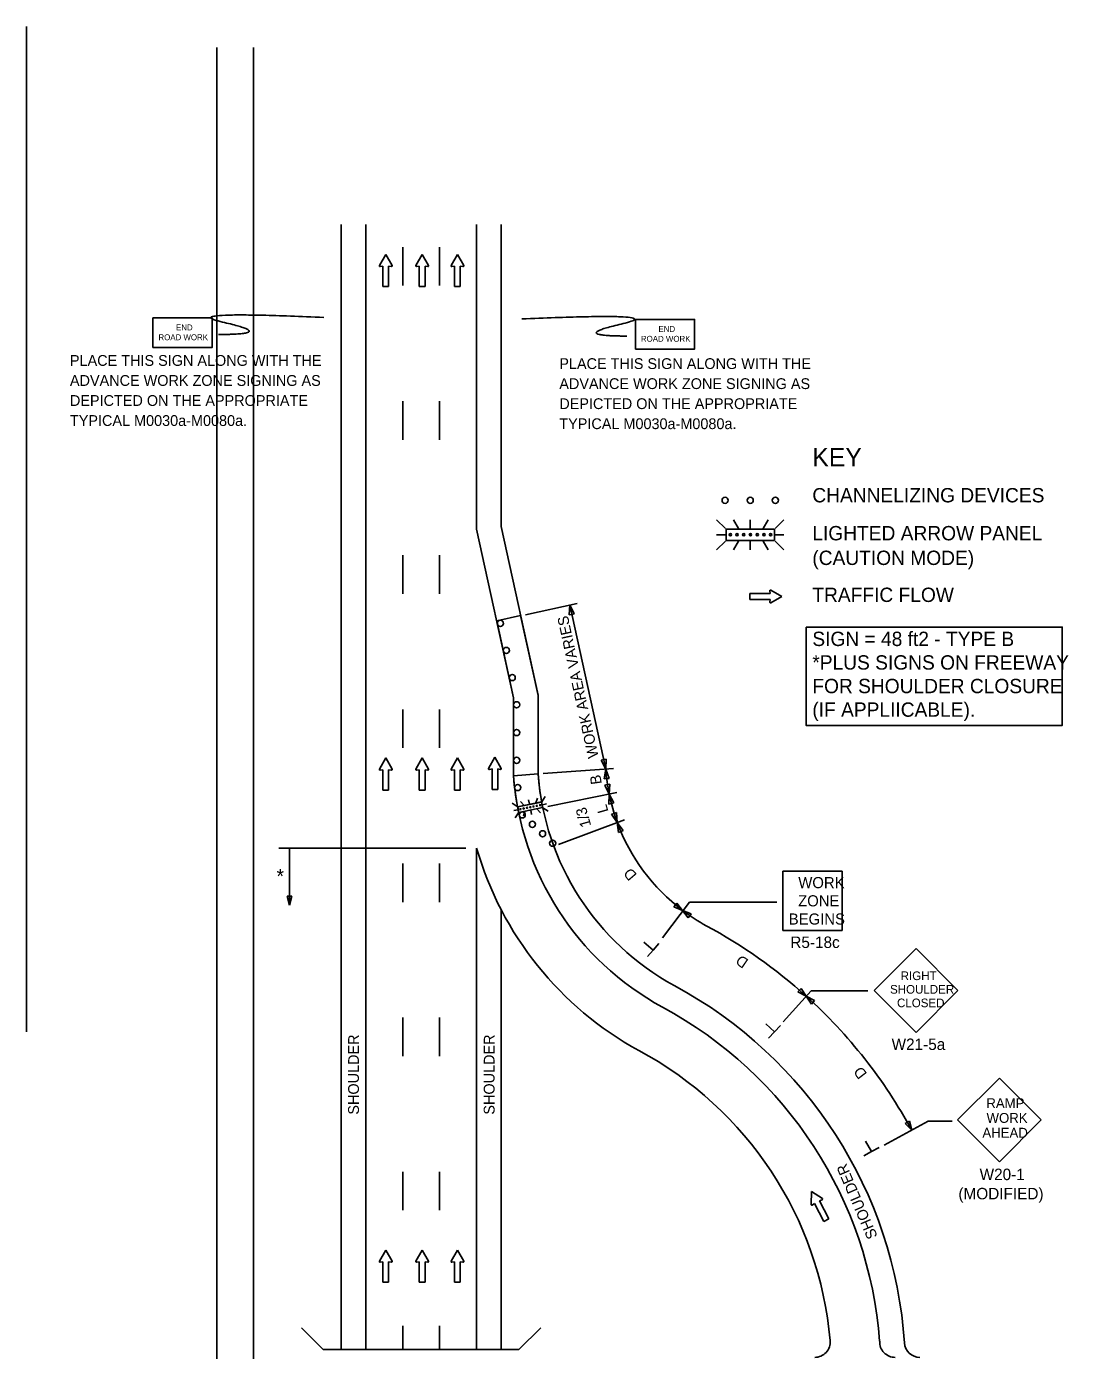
# Model space of a CAD drawing. Extents: x 16733 to 18471, y 4586 to 5876.
# Drawn here: x 16733 to 17409, y 5017 to 5876 of the extents above; entities that cross this region are included whole.
import ezdxf

# ---------------------------------------------------------------- set-up
doc = ezdxf.new("R2010")
doc.units = 0
for name, color, linetype in [('BORDER', 7, 'Continuous'), ('Level 10', 7, 'Continuous'), ('MT_SCRATCH_LEVEL_E', 7, 'Continuous'), ('PAVT_EDGE_EX', 7, 'Continuous'), ('TRAFFIC_SIGNS_PR', 7, 'Continuous'), ('TYPICAL_TEXT_DIMEN_EX', 7, 'Continuous')]:
    doc.layers.add(name, color=color, linetype=linetype)

msp = doc.modelspace()

# ---------------------------------------------------------------- linework, layer by layer
at = {"layer": 'BORDER'}
for p, q in [((17090.28, 5501.48), (17056.67, 5494.14)), ((17085.46, 5500.43), (17085.05, 5493.97)), ((17108.72, 5394.01), (17085.46, 5500.43)), ((17088.34, 5494.63), (17085.46, 5500.43)), ((17053.51, 5493.52), (17037.95, 5490.12)), ((17085.05, 5493.97), (17086.69, 5494.3)), ((17086.69, 5494.3), (17088.34, 5494.63)), ((17107.42, 5400.12), (17105.78, 5399.78)), ((17105.78, 5399.78), (17108.72, 5394.01)), ((17109.06, 5400.47), (17107.42, 5400.12)), ((17108.72, 5394.01), (17109.06, 5400.47)), ((17064.83, 5390.79), (17048.88, 5389.63)), ((17113.69, 5394.37), (17068.13, 5391.03)), ((17108.72, 5394.01), (17107.64, 5387.62)), ((17107.64, 5387.62), (17109.31, 5387.78)), ((17110.97, 5387.94), (17108.72, 5394.01)), ((17109.31, 5387.78), (17110.97, 5387.94)), ((17115.87, 5378.73), (17071.1, 5369.62)), ((17109.74, 5383.87), (17108.1, 5383.54)), ((17108.1, 5383.54), (17110.98, 5377.74)), ((17111.38, 5384.2), (17109.74, 5383.87)), ((17110.98, 5377.74), (17111.38, 5384.2)), ((17051.46, 5369.47), (17067.14, 5372.66)), ((17110.98, 5377.74), (17110.82, 5371.27)), ((17110.82, 5371.27), (17112.45, 5371.66)), ((17114.07, 5372.05), (17110.98, 5377.74)), ((17112.45, 5371.66), (17114.07, 5372.05)), ((17114.15, 5365.17), (17112.57, 5364.6)), ((17112.57, 5364.6), (17116.26, 5359.28)), ((17115.72, 5365.73), (17114.15, 5365.17)), ((17116.26, 5359.28), (17115.72, 5365.73)), ((17120.93, 5361.02), (17078.1, 5345.12)), ((17120.14, 5354.1), (17116.26, 5359.28)), ((17116.26, 5359.28), (17117.03, 5352.85)), ((17117.03, 5352.85), (17118.58, 5353.48)), ((17118.58, 5353.48), (17120.14, 5354.1)), ((17017.95, 5342.66), (16896.59, 5342.66)), ((16903.58, 5342.66), (16903.58, 5305.56)), ((16901.96, 5311.41), (16903.53, 5311.43)), ((16903.58, 5305.56), (16901.96, 5311.41)), ((16903.53, 5311.43), (16905.1, 5311.44)), ((16905.1, 5311.44), (16903.58, 5305.56)), ((17145.63, 5284.47), (17163.07, 5307.63)), ((17152.99, 5304.52), (17153.94, 5305.77)), ((17158.61, 5302.23), (17152.99, 5304.52)), ((17153.94, 5305.77), (17154.89, 5307.02)), ((17154.89, 5307.02), (17158.61, 5302.23)), ((17162.34, 5297.44), (17158.61, 5302.23)), ((17158.61, 5302.23), (17164.23, 5299.94)), ((17163.07, 5307.63), (17219.84, 5307.63)), ((17163.29, 5298.69), (17162.34, 5297.44)), ((17164.23, 5299.94), (17163.29, 5298.69)), ((17139.46, 5276.54), (17133.56, 5281.61)), ((17139.46, 5276.54), (17135.8, 5272.27)), ((17143.13, 5280.8), (17139.46, 5276.54)), ((17223.88, 5229.94), (17242.07, 5250.08)), ((17233.51, 5249.31), (17234.57, 5250.47)), ((17234.57, 5250.47), (17235.62, 5251.64)), ((17235.62, 5251.64), (17238.92, 5246.54)), ((17242.07, 5250.08), (17278.86, 5250.08)), ((17238.92, 5246.54), (17233.51, 5249.31)), ((17242.21, 5241.44), (17238.92, 5246.54)), ((17238.92, 5246.54), (17244.32, 5243.78)), ((17243.27, 5242.61), (17242.21, 5241.44)), ((17244.32, 5243.78), (17243.27, 5242.61)), ((17218.26, 5223.42), (17212.54, 5228.7)), ((17222.08, 5227.55), (17218.26, 5223.42)), ((17218.26, 5223.42), (17214.44, 5219.29)), ((17289.36, 5149.84), (17318, 5165.41)), ((17303.17, 5164.02), (17304.55, 5164.77)), ((17307.35, 5159.62), (17303.17, 5164.02)), ((17304.55, 5164.77), (17305.93, 5165.52)), ((17305.93, 5165.52), (17307.35, 5159.62)), ((17318, 5165.41), (17333.48, 5165.41)), ((17281.23, 5145.75), (17277.43, 5152.55)), ((17286.14, 5148.5), (17281.23, 5145.75)), ((17281.23, 5145.75), (17276.32, 5143.01))]:
    msp.add_line(p, q, dxfattribs=at)
msp.add_lwpolyline([(17238.81, 5486.09), (17405.03, 5486.09), (17405.03, 5422.27), (17238.81, 5422.27)], close=True, dxfattribs=at)
for centre, radius, start, end in [((17235.09, 5403.26), 126.71, 184.18699, 191.61938), ((17235.09, 5403.26), 126.71, 191.61938, 200.30842), ((17235.09, 5403.26), 126.71, 200.30842, 232.8734), ((17235.09, 5403.26), 126.71, 232.87354, 241.17586), ((17018.45, 5002.56), 328.83, 47.89858, 61.76587), ((17018.45, 5002.56), 328.83, 28.53082, 47.89848)]:
    msp.add_arc(centre, radius, start, end, dxfattribs=at)
at = {"layer": 'Level 10'}
msp.add_lwpolyline([(17037.95, 5490.12), (17048.88, 5440.12), (17048.88, 5389.63), (17064.83, 5390.79), (17064.83, 5441.74), (17053.51, 5493.52)], close=True, dxfattribs=at)
at = {"layer": 'MT_SCRATCH_LEVEL_E'}
for p, q in [((16965.96, 5727.95), (16961.85, 5720.71)), ((16970.11, 5720.71), (16965.96, 5727.95)), ((16989.58, 5727.95), (16985.47, 5720.71)), ((16993.73, 5720.71), (16989.58, 5727.95)), ((17012.44, 5727.95), (17008.33, 5720.71)), ((17016.58, 5720.71), (17012.44, 5727.95)), ((16962.33, 5720.03), (16964.11, 5720.35)), ((16964.11, 5720.35), (16964.11, 5707.09)), ((16967.85, 5707.09), (16967.85, 5720.35)), ((16967.85, 5720.35), (16969.63, 5720.03)), ((16985.95, 5720.03), (16987.73, 5720.35)), ((16987.73, 5720.35), (16987.73, 5707.09)), ((16991.47, 5707.09), (16991.47, 5720.35)), ((16991.47, 5720.35), (16993.25, 5720.03)), ((17008.81, 5720.03), (17010.58, 5720.35)), ((17010.58, 5720.35), (17010.58, 5707.09)), ((17014.33, 5707.09), (17014.33, 5720.35)), ((17014.33, 5720.35), (17016.1, 5720.03)), ((16964.11, 5707.09), (16967.85, 5707.09)), ((16987.73, 5707.09), (16991.47, 5707.09)), ((17010.58, 5707.09), (17014.33, 5707.09)), ((17215.49, 5507.82), (17202.24, 5507.82)), ((17202.24, 5507.82), (17202.24, 5504.08)), ((17215.49, 5507.82), (17202.24, 5507.82)), ((17202.24, 5507.82), (17202.24, 5504.08)), ((17215.18, 5509.6), (17215.49, 5507.82)), ((17215.18, 5509.6), (17215.49, 5507.82)), ((17223.1, 5505.97), (17215.86, 5510.08)), ((17223.1, 5505.97), (17215.86, 5510.08)), ((17202.24, 5504.08), (17215.49, 5504.08)), ((17202.24, 5504.08), (17215.49, 5504.08)), ((17215.49, 5504.08), (17215.18, 5502.3)), ((17215.49, 5504.08), (17215.18, 5502.3)), ((17215.86, 5501.82), (17223.1, 5505.97)), ((17215.86, 5501.82), (17223.1, 5505.97)), ((16965.96, 5401.18), (16961.85, 5393.94)), ((16970.11, 5393.94), (16965.96, 5401.18)), ((16989.58, 5401.18), (16985.47, 5393.94)), ((16993.73, 5393.94), (16989.58, 5401.18)), ((17012.44, 5401.18), (17008.33, 5393.94)), ((17016.58, 5393.94), (17012.44, 5401.18)), ((17036.82, 5401.63), (17032.71, 5394.39)), ((17040.96, 5394.39), (17036.82, 5401.63)), ((16962.33, 5393.25), (16964.11, 5393.57)), ((16964.11, 5393.57), (16964.11, 5380.31)), ((16967.85, 5380.31), (16967.85, 5393.57)), ((16967.85, 5393.57), (16969.63, 5393.25)), ((16985.95, 5393.25), (16987.73, 5393.57)), ((16987.73, 5393.57), (16987.73, 5380.31)), ((16991.47, 5380.31), (16991.47, 5393.57)), ((16991.47, 5393.57), (16993.25, 5393.25)), ((17008.81, 5393.25), (17010.58, 5393.57)), ((17010.58, 5393.57), (17010.58, 5380.31)), ((17014.33, 5380.31), (17014.33, 5393.57)), ((17014.33, 5393.57), (17016.1, 5393.25)), ((17033.19, 5393.71), (17034.97, 5394.02)), ((17034.97, 5394.02), (17034.97, 5380.77)), ((17038.71, 5380.77), (17038.71, 5394.02)), ((17038.71, 5394.02), (17040.48, 5393.71)), ((16964.11, 5380.31), (16967.85, 5380.31)), ((16987.73, 5380.31), (16991.47, 5380.31)), ((17010.58, 5380.31), (17014.33, 5380.31)), ((17034.97, 5380.77), (17038.71, 5380.77)), ((17242.32, 5119.76), (17242.01, 5111.44)), ((17249.34, 5115.25), (17242.32, 5119.76)), ((17242.76, 5111.06), (17244.19, 5112.16)), ((17244.19, 5112.16), (17250.3, 5100.39)), ((17247.51, 5113.88), (17249.23, 5114.42)), ((17253.62, 5102.12), (17247.51, 5113.88)), ((17250.3, 5100.39), (17253.62, 5102.12)), ((16965.96, 5081.87), (16961.85, 5074.63)), ((16970.11, 5074.63), (16965.96, 5081.87)), ((16989.58, 5081.87), (16985.47, 5074.63)), ((16993.73, 5074.63), (16989.58, 5081.87)), ((17012.44, 5081.87), (17008.33, 5074.63)), ((17016.58, 5074.63), (17012.44, 5081.87)), ((16962.33, 5073.94), (16964.11, 5074.26)), ((16964.11, 5074.26), (16964.11, 5061)), ((16967.85, 5061), (16967.85, 5074.26)), ((16967.85, 5074.26), (16969.63, 5073.94)), ((16985.95, 5073.94), (16987.73, 5074.26)), ((16987.73, 5074.26), (16987.73, 5061)), ((16991.47, 5061), (16991.47, 5074.26)), ((16991.47, 5074.26), (16993.25, 5073.94)), ((17008.81, 5073.94), (17010.58, 5074.26)), ((17010.58, 5074.26), (17010.58, 5061)), ((17014.33, 5061), (17014.33, 5074.26)), ((17014.33, 5074.26), (17016.1, 5073.94)), ((16964.11, 5061), (16967.85, 5061)), ((16987.73, 5061), (16991.47, 5061)), ((17010.58, 5061), (17014.33, 5061))]:
    msp.add_line(p, q, dxfattribs=at)
for centre, start, end in [((16962.26, 5720.49), 150.42484, 279.96381), ((16969.7, 5720.49), 260.03619, 29.77312), ((16985.88, 5720.49), 150.42484, 279.96381), ((16993.32, 5720.49), 260.03619, 29.77312), ((17008.73, 5720.49), 150.42484, 279.96381), ((17016.17, 5720.49), 260.03619, 29.77312), ((17215.64, 5509.67), 60.42484, 189.96381), ((17215.64, 5509.67), 60.42484, 189.96381), ((17215.64, 5502.23), 170.03619, 299.77312), ((17215.64, 5502.23), 170.03619, 299.77312), ((16962.26, 5393.71), 150.42484, 279.96381), ((16969.7, 5393.71), 260.03619, 29.77312), ((16985.88, 5393.71), 150.42484, 279.96381), ((16993.32, 5393.71), 260.03619, 29.77312), ((17008.73, 5393.71), 150.42484, 279.96381), ((17016.17, 5393.71), 260.03619, 29.77312), ((17033.11, 5394.17), 150.42484, 279.96381), ((17040.55, 5394.17), 260.03619, 29.77312), ((17249.08, 5114.86), 287.48456, 57.22148), ((17242.48, 5111.43), 177.8732, 307.41217), ((16962.26, 5074.4), 150.42484, 279.96381), ((16969.7, 5074.41), 260.03619, 29.77312), ((16985.88, 5074.4), 150.42484, 279.96381), ((16993.32, 5074.41), 260.03619, 29.77312), ((17008.73, 5074.4), 150.42484, 279.96381), ((17016.17, 5074.41), 260.03619, 29.77312)]:
    msp.add_arc(centre, 0.463, start, end, dxfattribs=at)
at = {"layer": 'PAVT_EDGE_EX'}
for p, q in [((16936.94, 5747.37), (16936.94, 5017.24)), ((16952.94, 5747.37), (16952.94, 5017.24)), ((17024.94, 5747.37), (17024.94, 5549.62)), ((17040.85, 5747.37), (17040.85, 5551.24)), ((17064.79, 5441.94), (17040.85, 5551.44)), ((17048.88, 5440.12), (17024.94, 5549.62)), ((17048.88, 5389.63), (17048.88, 5440.12)), ((17064.83, 5389.63), (17064.83, 5441.74)), ((17064.83, 5390.79), (17048.88, 5389.63)), ((17051.46, 5369.47), (17067.14, 5372.66)), ((17024.94, 5342.66), (17024.94, 5017.24)), ((17040.94, 5302.56), (17040.94, 5017.24)), ((16911.3, 5031.38), (16925.44, 5017.24)), ((17066.58, 5031.38), (17052.44, 5017.24)), ((16925.44, 5017.24), (17052.44, 5017.24))]:
    msp.add_line(p, q, dxfattribs=at)
for centre, radius, start, end in [((17235.09, 5403.26), 186.71, 184.18699, 241.32804), ((17235.09, 5403.26), 186.71, 184.18699, 190.42684), ((17235.09, 5403.26), 170.71, 184.18699, 241.32804), ((17235.09, 5403.26), 170.71, 184.18699, 190.32597), ((17235.09, 5403.26), 218.71, 196.08461, 241.32804), ((17018.45, 5002.56), 284.8, 3.82656, 61.76587), ((17018.45, 5002.56), 268.8, 4.28948, 61.79192), ((17018.45, 5002.56), 236.8, 4.97638, 61.85461), ((17244.4, 5022.24), 10, 270, 4.97638), ((17296.56, 5022.24), 10.03, 177.54481, 270), ((17312.6, 5022.24), 10, 183.82656, 270)]:
    msp.add_arc(centre, radius, start, end, dxfattribs=at)
at = {"layer": 'TRAFFIC_SIGNS_PR'}
for p, q in [((16732.78, 5223.5), (16732.78, 5875.82)), ((16856.22, 4907.7), (16856.22, 5862.15)), ((16880.22, 4907.7), (16880.22, 5862.15)), ((17180.73, 5555.69), (17186.37, 5550.06)), ((17194.91, 5550.06), (17191.65, 5555.7)), ((17202.54, 5550.06), (17202.54, 5555.7)), ((17210.81, 5550.06), (17214.07, 5555.7)), ((17218.71, 5550.06), (17224.35, 5555.7)), ((17186.37, 5545.99), (17180.73, 5545.99)), ((17180.73, 5536.29), (17186.37, 5541.93)), ((17189.64, 5545.99), (17189.64, 5545.99)), ((17191.6, 5536.29), (17194.86, 5541.93)), ((17193.99, 5545.99), (17193.99, 5545.99)), ((17198.34, 5545.99), (17198.34, 5545.99)), ((17202.54, 5541.93), (17202.54, 5536.29)), ((17202.69, 5545.99), (17202.69, 5545.99)), ((17207.03, 5545.99), (17207.03, 5545.99)), ((17214.12, 5536.29), (17210.86, 5541.93)), ((17211.38, 5545.99), (17211.38, 5545.99)), ((17215.73, 5545.99), (17215.73, 5545.99)), ((17218.71, 5545.99), (17224.35, 5545.99)), ((17218.71, 5541.93), (17224.35, 5536.29)), ((17048.88, 5440.12), (17048.88, 5440.12)), ((17048.03, 5371.78), (17051.35, 5369.59)), ((17055.54, 5370.44), (17053.38, 5372.88)), ((17059.28, 5371.2), (17058.71, 5373.96)), ((17063.33, 5372.02), (17064.36, 5375.11)), ((17064.01, 5370.09), (17064.01, 5370.09)), ((17066.14, 5370.52), (17066.14, 5370.52)), ((17067.2, 5372.81), (17069.4, 5376.14)), ((17067.6, 5370.82), (17070.37, 5371.38)), ((17051.76, 5367.59), (17049, 5367.03)), ((17049.96, 5362.28), (17052.16, 5365.6)), ((17053.36, 5367.92), (17053.36, 5367.92)), ((17055.29, 5363.36), (17056.32, 5366.45)), ((17055.49, 5368.35), (17055.49, 5368.35)), ((17057.62, 5368.79), (17057.62, 5368.79)), ((17059.75, 5369.22), (17059.75, 5369.22)), ((17060.09, 5367.22), (17060.65, 5364.45)), ((17061.88, 5369.65), (17061.88, 5369.65)), ((17066.32, 5365.61), (17064.16, 5368.04)), ((17068.01, 5368.83), (17071.33, 5366.62)), ((17223.72, 5289.31), (17223.72, 5327.71)), ((17223.72, 5327.71), (17262.12, 5327.71)), ((17262.12, 5289.31), (17262.12, 5327.71)), ((17223.72, 5289.31), (17262.12, 5289.31)), ((17310.19, 5277.44), (17283.04, 5250.28)), ((17337.35, 5250.28), (17310.19, 5277.44)), ((17283.04, 5250.28), (17310.19, 5223.13)), ((17310.19, 5223.13), (17337.35, 5250.28)), ((17364.2, 5193.46), (17337.05, 5166.3)), ((17391.36, 5166.3), (17364.2, 5193.46)), ((17337.05, 5166.3), (17364.2, 5139.15)), ((17364.2, 5139.15), (17391.36, 5166.3))]:
    msp.add_line(p, q, dxfattribs=at)
for points in [[(16976.94, 5707.7), (16976.94, 5732.7)], [(17000.94, 5707.7), (17000.94, 5732.7)], [(16976.94, 5607.7), (16976.94, 5632.7)], [(17000.94, 5607.7), (17000.94, 5632.7)], [(16976.94, 5507.7), (16976.94, 5532.7)], [(17000.94, 5507.7), (17000.94, 5532.7)], [(16976.94, 5407.7), (16976.94, 5432.7)], [(17000.94, 5407.7), (17000.94, 5432.7)], [(16976.94, 5307.7), (16976.94, 5332.7)], [(17000.94, 5307.7), (17000.94, 5332.7)], [(16976.94, 5207.7), (16976.94, 5232.7)], [(17000.94, 5207.7), (17000.94, 5232.7)], [(16976.94, 5107.7), (16976.94, 5132.7)], [(17000.94, 5107.7), (17000.94, 5132.7)], [(16976.94, 5017.24), (16976.94, 5032.7)], [(17000.94, 5017.24), (17000.94, 5032.7)]]:
    msp.add_lwpolyline(points, dxfattribs=at)
for points in [[(16814.83, 5667.5), (16853.23, 5667.5), (16853.23, 5686.7), (16814.83, 5686.7)], [(17127.95, 5666.51), (17166.35, 5666.51), (17166.35, 5685.71), (17127.95, 5685.71)], [(17218.25, 5542.39), (17186.83, 5542.39), (17186.83, 5549.59), (17218.25, 5549.59)], [(17067.74, 5369.01), (17052.34, 5365.88), (17051.63, 5369.4), (17067.02, 5372.53)]]:
    msp.add_lwpolyline(points, close=True, dxfattribs=at)
for centre, radius in [((17186.23, 5568.39), 2), ((17202.53, 5568.39), 2), ((17218.83, 5568.39), 2), ((17189.68, 5545.99), 0.758), ((17193.99, 5545.99), 0.758), ((17198.34, 5545.99), 0.758), ((17202.69, 5545.99), 0.758), ((17207.03, 5545.99), 0.758), ((17211.38, 5545.99), 0.758), ((17215.73, 5545.99), 0.758), ((17040.35, 5488.52), 2), ((17044.19, 5470.94), 2), ((17048.03, 5453.35), 2), ((17050.88, 5435.66), 2), ((17050.88, 5417.66), 2), ((17050.88, 5399.66), 2), ((17051.61, 5381.98), 2), ((17061.88, 5369.65), 0.379), ((17064.01, 5370.09), 0.379), ((17066.14, 5370.52), 0.379), ((17054.55, 5364.23), 2), ((17053.38, 5367.92), 0.379), ((17055.49, 5368.35), 0.379), ((17057.62, 5368.79), 0.379), ((17059.75, 5369.22), 0.379), ((17061.15, 5358.11), 2), ((17067.74, 5351.98), 2), ((17074.33, 5345.86), 2)]:
    msp.add_circle(centre, radius, dxfattribs=at)
for points in [[(16857.49, 5675.96), (16895.28, 5675.96), (16827.26, 5691.43), (16925.74, 5687.04)], [(17122.5, 5674.95), (17084.72, 5674.95), (17152.73, 5690.43), (17054.26, 5686.04)]]:
    msp.add_open_spline(points, degree=2, dxfattribs=at)

# ---------------------------------------------------------------- texts
at = {"layer": 'BORDER'}
for s, rotation, p in [('WORK AREA VARIES', 102.33096, (17104.2, 5401.94)), ('B', 97.90121, (17106.18, 5384.45)), ('L', 105.96425, (17110.57, 5366.51)), ('1/3', 105.96425, (17099.38, 5357.29)), ('D', 130.40524, (17129.38, 5325.34)), ('D', 145.62367, (17201.89, 5269.96)), ('SHOULDER', 90, (16948.54, 5169.73)), ('SHOULDER', 90, (17036.58, 5169.73)), ('D', 127.62367, (17278.7, 5196.28)), ('SHOULDER', 113.35307, (17285.32, 5090.8))]:
    msp.add_text(s, height=7, rotation=rotation, dxfattribs=at).set_placement(p)
for s, p in [('SIGN = 48 ft2 - TYPE B', (17242.83, 5473.81)), ('*PLUS SIGNS ON FREEWAY', (17242.83, 5458.51)), ('FOR SHOULDER CLOSURE', (17242.83, 5443.21)), ('(IF APPLIICABLE).', (17242.83, 5427.91)), ('*', (16895.11, 5319.82))]:
    msp.add_text(s, height=9.3, dxfattribs=at).set_placement(p)
at = {"layer": 'TRAFFIC_SIGNS_PR'}
for s, height, p in [('END', 3.831, (16829.83, 5678.62)), ('END', 3.831, (17142.95, 5677.64)), ('ROAD WORK', 3.831, (16818.44, 5672.24)), ('ROAD WORK', 3.831, (17131.56, 5671.25)), ('PLACE THIS SIGN ALONG WITH THE', 7, (16760.99, 5655.61)), ('PLACE THIS SIGN ALONG WITH THE', 7, (17078.61, 5653.56)), ('ADVANCE WORK ZONE SIGNING AS', 7, (16760.99, 5642.61)), ('ADVANCE WORK ZONE SIGNING AS', 7, (17078.61, 5640.56)), ('DEPICTED ON THE APPROPRIATE', 7, (16760.99, 5629.61)), ('DEPICTED ON THE APPROPRIATE', 7, (17078.61, 5627.56)), ('TYPICAL M0030a-M0080a.', 7, (16760.99, 5616.61)), ('TYPICAL M0030a-M0080a.', 7, (17078.61, 5614.56)), ('WORK', 7.217, (17233.72, 5316.68)), ('ZONE', 7.217, (17233.6, 5304.87)), ('BEGINS', 7.217, (17227.53, 5293.06)), ('R5-18c', 7.44, (17228.53, 5277.87)), ('RIGHT', 5.6, (17300.17, 5257.04)), ('SHOULDER', 5.6, (17293.27, 5248.24)), ('CLOSED', 5.6, (17297.79, 5239.44)), ('W21-5a', 7.44, (17294.27, 5211.69)), ('RAMP', 6.4, (17355.76, 5173.99)), ('WORK', 6.4, (17355.9, 5164.39)), ('AHEAD', 6.4, (17353.21, 5154.79)), ('W20-1', 7.44, (17351.4, 5127.25)), ('(MODIFIED)', 7.44, (17337.64, 5114.77))]:
    msp.add_text(s, height=height, dxfattribs=at).set_placement(p)
at = {"layer": 'TYPICAL_TEXT_DIMEN_EX'}
for s, height, p in [('KEY', 12, (17242.83, 5590.39)), ('CHANNELIZING DEVICES', 9.3, (17242.83, 5567.02)), ('LIGHTED ARROW PANEL', 9.3, (17242.83, 5542.39)), ('(CAUTION MODE)', 9.3, (17242.83, 5526.39)), ('TRAFFIC FLOW', 9.3, (17242.83, 5502.39))]:
    msp.add_text(s, height=height, dxfattribs=at).set_placement(p)

doc.saveas('drawing.dxf')
